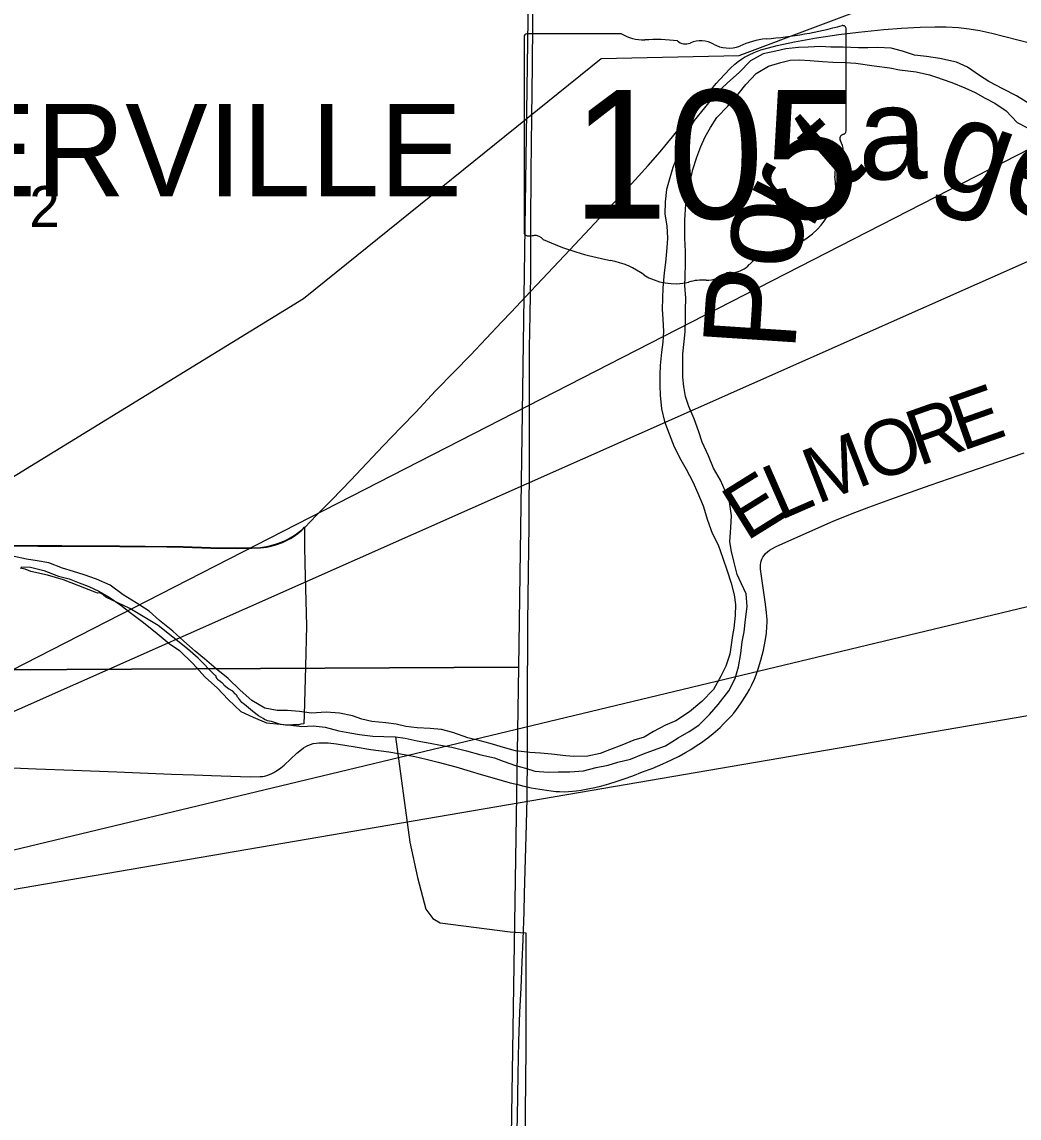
# Model space of a CAD drawing. Extents: x -8.3 to 42.1, y 0 to 22.
# Drawn here: x 6.351 to 7.372, y 16.882 to 18.005 of the extents above; entities that cross this region are included whole.
import ezdxf

# ---------------------------------------------------------------- set-up
doc = ezdxf.new("R2010")
doc.units = 0
for name, color, linetype in [('GM_X_Corporation', 7, 'Continuous'), ('GM_X_Corporation_Text', 7, 'Continuous'), ('GM_X_Major_River', 7, 'Continuous'), ('GM_X_Major_River_Text', 7, 'Continuous'), ('GM_X_Minor_River', 7, 'Continuous'), ('GM_X_Rail_Line', 7, 'Continuous'), ('GM_X_Section', 7, 'Continuous'), ('GM_X_Section_Text', 7, 'Continuous'), ('GM_X_State_Location', 7, 'Continuous'), ('GM_X_State_Route', 7, 'Continuous'), ('GM_X_State_Shield', 7, 'Continuous'), ('GM_X_Township_Road', 7, 'Continuous'), ('GM_X_Township_Road_Text', 7, 'Continuous'), ('SH_Text', 7, 'Continuous')]:
    doc.layers.add(name, color=color, linetype=linetype)

msp = doc.modelspace()

# ---------------------------------------------------------------- linework, layer by layer
at = {"layer": 'GM_X_Corporation'}
msp.add_lwpolyline([(6.3281, 17.4687), (6.3669, 17.4683), (6.3917, 17.4683), (6.4507, 17.4679), (6.4771, 17.4678), (6.4989, 17.4675), (6.5159, 17.4672), (6.5439, 17.4663), (6.5718, 17.4659), (6.5857, 17.466), (6.595, 17.4665), (6.6011, 17.4674), (6.6055, 17.4683), (6.6114, 17.47), (6.6172, 17.4721), (6.6214, 17.474), (6.6254, 17.4762), (6.6294, 17.4786), (6.6331, 17.4813), (6.6372, 17.4846), (6.6401, 17.4875), (6.6402, 17.4676), (6.6406, 17.4498), (6.6423, 17.386), (6.6411, 17.3446), (6.6398, 17.2948), (6.6393, 17.2857), (6.6363, 17.2852), (6.6342, 17.2848), (6.6324, 17.2846), (6.6282, 17.2846), (6.6275, 17.2845), (6.6268, 17.2844), (6.6252, 17.2843), (6.6233, 17.2843), (6.622, 17.2843), (6.6206, 17.2845), (6.6183, 17.2848), (6.6162, 17.285), (6.6146, 17.2854), (6.6142, 17.2854), (6.6136, 17.2856), (6.6134, 17.2857), (6.6123, 17.2862), (6.6104, 17.2867), (6.6093, 17.2871), (6.6084, 17.2874), (6.6064, 17.288), (6.6022, 17.2889), (6.6016, 17.2891), (6.5991, 17.2903), (6.5977, 17.2911), (6.5931, 17.294), (6.5915, 17.2949), (6.5884, 17.2973), (6.5872, 17.2983), (6.5869, 17.2988), (6.5785, 17.3054), (6.576, 17.3077), (6.5729, 17.3116), (6.5722, 17.3123), (6.5716, 17.3131), (6.5712, 17.3138), (6.571, 17.3143), (6.5705, 17.3149), (6.5696, 17.3156), (6.569, 17.3165), (6.5668, 17.319), (6.5624, 17.3217), (6.5613, 17.3224), (6.5592, 17.3239), (6.558, 17.325), (6.557, 17.3262), (6.556, 17.3272), (6.5555, 17.3277), (6.5539, 17.329), (6.552, 17.3303), (6.5519, 17.3304), (6.5513, 17.3309), (6.5509, 17.3316), (6.5505, 17.3323), (6.5502, 17.3329), (6.5496, 17.3332), (6.5496, 17.3347), (6.5489, 17.3352), (6.5484, 17.3357), (6.5313, 17.3529), (6.5204, 17.3626), (6.4902, 17.3865), (6.4613, 17.4039), (6.4367, 17.4155), (6.4344, 17.4174), (6.4327, 17.419), (6.4307, 17.4198), (6.4282, 17.4197), (6.4231, 17.4215), (6.3935, 17.4332), (6.3769, 17.4381), (6.36, 17.4419), (6.354, 17.4441), (6.349, 17.4451)], dxfattribs=at)
at = {"layer": 'GM_X_Major_River'}
for points in [[(7.3833, 17.9203), (7.3692, 17.929), (7.355, 17.9362), (7.3408, 17.9437), (7.3311, 17.95), (7.3188, 17.9583), (7.3075, 17.9635), (7.2906, 17.9673), (7.277, 17.9692), (7.2645, 17.9706), (7.2525, 17.9747), (7.2407, 17.9777), (7.2269, 17.9787), (7.217, 17.9782), (7.2072, 17.9781), (7.1917, 17.9788), (7.1788, 17.9788), (7.1686, 17.9794), (7.1557, 17.9789), (7.1458, 17.9784), (7.1329, 17.9772), (7.1226, 17.9748), (7.1097, 17.9721), (7.0966, 17.9648), (7.085, 17.953), (7.073, 17.9422), (7.061, 17.9308), (7.0496, 17.9166), (7.0391, 17.9036), (7.0312, 17.8905), (7.0256, 17.8785), (7.0223, 17.8687), (7.0171, 17.8556), (7.0133, 17.8427), (7.0108, 17.8329), (7.0094, 17.8204), (7.0091, 17.8079), (7.011, 17.7957), (7.0119, 17.7832), (7.0112, 17.7733), (7.0097, 17.7582), (7.0083, 17.7476), (7.0068, 17.7325), (7.0063, 17.7105), (7.0068, 17.7002), (7.0076, 17.6877), (7.0069, 17.6767), (7.0055, 17.6665), (7.0041, 17.6528), (7.0038, 17.6433), (7.0039, 17.632), (7.0041, 17.6225), (7.0056, 17.6084), (7.0087, 17.5954), (7.0133, 17.5828), (7.0187, 17.5694), (7.0255, 17.5563), (7.031, 17.5467), (7.0378, 17.5336)], [(7.0915, 17.3926), (7.0934, 17.4059), (7.0922, 17.4188), (7.0875, 17.4292), (7.0832, 17.4388), (7.0798, 17.4525), (7.0774, 17.4624), (7.0757, 17.4723), (7.0765, 17.4867), (7.0771, 17.4989), (7.0752, 17.513), (7.0709, 17.5244), (7.0659, 17.5352), (7.059, 17.5475), (7.0537, 17.5602), (7.0472, 17.5744), (7.0437, 17.5847), (7.0391, 17.5981), (7.0337, 17.6107), (7.0302, 17.6211), (7.0285, 17.6314), (7.0276, 17.6409), (7.0276, 17.6545), (7.0275, 17.6648), (7.0289, 17.6773), (7.0299, 17.6871), (7.0302, 17.6989), (7.0301, 17.7099), (7.0304, 17.7216), (7.0296, 17.7346), (7.0298, 17.744), (7.0301, 17.7569), (7.0301, 17.7695), (7.0296, 17.7831), (7.0294, 17.8021), (7.0305, 17.8177), (7.0323, 17.8286), (7.0345, 17.8399), (7.0378, 17.8535), (7.0419, 17.8663), (7.046, 17.8772), (7.0504, 17.887), (7.0559, 17.8967), (7.0623, 17.9068), (7.0735, 17.9183), (7.084, 17.9308), (7.092, 17.9405), (7.1024, 17.9518), (7.1151, 17.9594), (7.1277, 17.9633), (7.1372, 17.9654), (7.1467, 17.9659), (7.1577, 17.9652), (7.1705, 17.9642), (7.1811, 17.9635), (7.1935, 17.9632), (7.2045, 17.9626), (7.2234, 17.9598), (7.2392, 17.9576), (7.2494, 17.9558), (7.2664, 17.9535), (7.28, 17.9505), (7.286, 17.9484), (7.3029, 17.9427), (7.316, 17.9371), (7.3268, 17.9323), (7.3369, 17.9267), (7.347, 17.9216), (7.3586, 17.9137), (7.3696, 17.9017), (7.3797, 17.8965)], [(7.0378, 17.5336), (7.0429, 17.5221), (7.0482, 17.5091), (7.0528, 17.4945), (7.0574, 17.4811), (7.0635, 17.4692), (7.0685, 17.4554), (7.0727, 17.4424), (7.0769, 17.4298), (7.08, 17.418), (7.0813, 17.4081), (7.081, 17.3967), (7.0797, 17.3838), (7.0784, 17.3763), (7.0755, 17.357), (7.0714, 17.3449), (7.0662, 17.3344), (7.0587, 17.3209), (7.047, 17.3087), (7.0343, 17.298), (7.0204, 17.2889), (7.0097, 17.2842), (6.9974, 17.2777), (6.9878, 17.2722), (6.9771, 17.269), (6.9649, 17.264), (6.9523, 17.259), (6.9427, 17.2554), (6.9301, 17.2527), (6.9159, 17.2521), (6.9075, 17.2529), (6.8931, 17.2548), (6.8818, 17.2558), (6.8708, 17.2564), (6.8561, 17.2579), (6.844, 17.2613), (6.8301, 17.2654), (6.82, 17.2683), (6.8072, 17.2713), (6.7918, 17.2769), (6.7805, 17.2799), (6.7688, 17.2809), (6.7555, 17.2816), (6.7438, 17.283), (6.734, 17.2852), (6.7235, 17.2866), (6.7091, 17.2881), (6.6989, 17.2906), (6.6892, 17.2939), (6.676, 17.2965), (6.6624, 17.2975), (6.6472, 17.2968), (6.6351, 17.2982), (6.6227, 17.2993), (6.6121, 17.2995), (6.5996, 17.3017), (6.5862, 17.3096), (6.5743, 17.3202), (6.5618, 17.3322), (6.5495, 17.342), (6.5376, 17.3522), (6.528, 17.36), (6.5165, 17.3705), (6.5054, 17.3807), (6.4917, 17.3916), (6.4809, 17.401), (6.4679, 17.4097), (6.4544, 17.418), (6.4411, 17.4278), (6.4273, 17.4338), (6.4144, 17.4383), (6.4035, 17.4416), (6.3923, 17.4453), (6.3784, 17.4506), (6.3663, 17.4527), (6.3554, 17.4545), (6.3429, 17.4571)], [(6.3499, 17.4467), (6.3597, 17.4461), (6.3733, 17.4427), (6.3883, 17.437), (6.3992, 17.4341), (6.4093, 17.4301), (6.4194, 17.4264), (6.4295, 17.4216), (6.44, 17.4153), (6.4519, 17.4074), (6.4616, 17.3996), (6.4753, 17.3894), (6.4891, 17.3784), (6.5017, 17.3679), (6.5121, 17.3608), (6.5258, 17.3475), (6.5383, 17.3336), (6.5509, 17.3223), (6.562, 17.3106), (6.5749, 17.2985), (6.5877, 17.2925), (6.6012, 17.2869), (6.6151, 17.2854), (6.6261, 17.2844), (6.6374, 17.283), (6.6488, 17.2835), (6.6613, 17.2824), (6.6752, 17.2786), (6.6865, 17.2765), (6.6963, 17.2747), (6.7099, 17.2732), (6.7212, 17.2726), (6.7333, 17.2723), (6.7431, 17.2709), (6.7556, 17.2683), (6.7689, 17.266), (6.7793, 17.264), (6.791, 17.2618), (6.8061, 17.258), (6.8207, 17.2539), (6.8347, 17.2509), (6.8435, 17.2474), (6.8561, 17.2431), (6.8662, 17.2402), (6.876, 17.2373), (6.8896, 17.2362), (6.8998, 17.2364), (6.9116, 17.2365), (6.9256, 17.2376), (6.9386, 17.2411), (6.9511, 17.2435), (6.9608, 17.2463), (6.974, 17.2494), (6.987, 17.2551), (6.9973, 17.2587), (7.0096, 17.2633), (7.0226, 17.2713), (7.0338, 17.2779), (7.0438, 17.2845), (7.0547, 17.2952), (7.0636, 17.3056), (7.0746, 17.3194), (7.0809, 17.3322), (7.0843, 17.3442), (7.0869, 17.3578), (7.0883, 17.3696), (7.0901, 17.3798), (7.0915, 17.3926)]]:
    msp.add_lwpolyline(points, dxfattribs=at)
at = {"layer": 'GM_X_Minor_River'}
msp.add_lwpolyline([(6.7333, 17.2723), (6.7481, 17.1645), (6.7559, 17.1283), (6.7642, 17.0958), (6.7715, 17.0862), (6.779, 17.0818), (6.8507, 17.0725), (6.8666, 17.0717), (6.8667, 16.9529), (6.8644, 16.7253), (6.8617, 16.5857), (6.861, 16.4802), (6.8584, 16.374), (6.8579, 16.325), (6.8551, 16.2708), (6.853, 16.1878), (6.8511, 16.0815), (6.8504, 15.9601), (6.848, 15.8175)], dxfattribs=at)
at = {"layer": 'GM_X_Rail_Line'}
msp.add_lwpolyline([(5.9044, 17.3082), (6.0693, 17.3942), (6.218, 17.4628), (6.6389, 17.7213), (6.9437, 17.9671), (7.085, 17.9703), (7.2495, 18.0325), (7.9103, 18.3409)], dxfattribs=at)
at = {"layer": 'GM_X_Section'}
for points in [[(5.9121, 18.3219), (6.8731, 18.3158), (6.8593, 17.3438), (5.8682, 17.3386), (5.8932, 18.3221)], [(6.8593, 17.3438), (6.8436, 16.3404), (5.8503, 16.3424), (5.8682, 17.3386)]]:
    msp.add_lwpolyline(points, close=True, dxfattribs=at)
at = {"layer": 'GM_X_State_Route'}
for points in [[(6.6404, 17.4869), (6.6522, 17.499), (6.6681, 17.5152), (6.6875, 17.5354), (6.7206, 17.5705), (6.739, 17.5895), (6.7542, 17.605), (6.7742, 17.6267), (6.7937, 17.6468), (6.81, 17.6635), (6.842, 17.6975), (6.8517, 17.7075), (6.8715, 17.7285), (6.878, 17.7354), (6.9117, 17.7712), (6.9573, 17.8197), (6.9787, 17.8429), (6.992, 17.8576), (7.0042, 17.8717), (7.0169, 17.887), (7.025, 17.8972), (7.0321, 17.9059), (7.0492, 17.9265), (7.0617, 17.9418), (7.07, 17.951), (7.0761, 17.9572), (7.0806, 17.9613), (7.0842, 17.9642), (7.0875, 17.9666), (7.0906, 17.9685), (7.0954, 17.9711), (7.1005, 17.9734), (7.1074, 17.976), (7.1151, 17.9783), (7.1241, 17.9806), (7.1417, 17.9842), (7.1643, 17.9884), (7.187, 17.9918), (7.2074, 17.9943), (7.2333, 17.9969), (7.2513, 17.9983), (7.2705, 17.9993), (7.2854, 17.9997), (7.2972, 17.9996), (7.3096, 17.999), (7.3206, 17.9978), (7.3316, 17.996), (7.3437, 17.9933), (7.4238, 17.9728)], [(6.2852, 17.4687), (6.3283, 17.4682), (6.3671, 17.4678), (6.392, 17.4677), (6.4509, 17.4673), (6.4773, 17.4672), (6.4991, 17.4669), (6.5162, 17.4666), (6.5441, 17.4658), (6.572, 17.4654), (6.586, 17.4655), (6.5952, 17.466), (6.6013, 17.4668), (6.6058, 17.4678), (6.6117, 17.4695), (6.6174, 17.4716), (6.6216, 17.4735), (6.6257, 17.4756), (6.6296, 17.4781), (6.6333, 17.4807), (6.6374, 17.4841), (6.6404, 17.4869)]]:
    msp.add_lwpolyline(points, dxfattribs=at)
at = {"layer": 'GM_X_State_Shield'}
for p, q in [((6.865, 17.9892), (6.865, 17.7891)), ((6.9647, 17.9927), (6.8682, 17.9927)), ((7.1946, 17.893), (7.1946, 17.9976)), ((7.1945, 17.893), (7.1946, 17.893))]:
    msp.add_line(p, q, dxfattribs=at)
for centre, major_axis, start_param, end_param in [((7.0772, 18.2655), (0.3495, 0), 4.814394, 5.042369), ((7.1909, 17.9981), (0.00367, 0), 6.141152, 7.989035), ((6.8688, 17.9897), (0.00382, 0), 1.712693, 3.28349), ((6.9877, 18.0159), (0.037, 0), 4.042523, 4.731795), ((7, 17.8803), (0.133, 0), 1.404758, 1.657858), ((7.0302, 17.9907), (0.0107, 0), 3.836095, 5.185415), ((7.0459, 17.9676), (0.0222, 0), 0.950623, 2.079405), ((7.0746, 17.9993), (0.0267, 0), 4.081561, 5.145723), ((7.1217, 17.9316), (0.0703, 0), 1.699011, 2.107814), ((7.1937, 17.8853), (0.00568, 0), 1.883978, 3.671073), ((7.1906, 17.8926), (0.00393, 0), 5.05454, 6.418171), ((7.1576, 17.872), (0.0341, 0), 5.934695, 6.695948), ((7.2077, 17.8492), (0.0248, 0), 2.387724, 3.262537), ((7.0967, 17.8358), (0.0874, 0), 5.101752, 6.440018), ((6.8688, 17.7887), (0.00385, 0), 3.00124, 4.508301), ((6.8694, 17.8092), (0.0294, 0), 4.665946, 4.897461), ((6.8754, 17.7776), (0.0106, 0), 0.519207, 1.627899), ((7.0092, 17.9574), (0.2524, 0), 4.195997, 4.488961), ((7.1336, 17.7329), (0.0479, 0), 1.647645, 2.488434), ((6.934, 17.6992), (0.079, 0), 0.823519, 1.323587), ((7.0729, 17.7697), (0.0282, 0), 4.937069, 5.64225), ((7.0194, 17.7766), (0.0501, 0), 4.026481, 4.996735), ((7.052, 17.7616), (0.0267, 0), 4.691044, 5.507374), ((7.0761, 17.7422), (0.00752, 0), 1.147584, 2.315152), ((7.0483, 17.7074), (0.0412, 0), 1.495662, 1.94098)]:
    msp.add_ellipse(centre, major_axis=major_axis, ratio=0.8, start_param=start_param, end_param=end_param, dxfattribs=at)
at = {"layer": 'GM_X_Township_Road'}
for points in [[(6.8715, 17.7285), (6.8719, 17.7424), (6.8719, 17.7641), (6.8719, 17.7968), (6.8722, 17.8512), (6.8728, 17.9071), (6.8734, 17.96), (6.8743, 18.047), (6.8751, 18.1201), (6.8762, 18.2055), (6.8767, 18.232), (6.8771, 18.2568), (6.8776, 18.2817), (6.8784, 18.3004), (6.8786, 18.3057)], [(6.8681, 17.2212), (6.8683, 17.2435), (6.8684, 17.273), (6.8684, 17.301), (6.8688, 17.3896), (6.8693, 17.4409), (6.87, 17.4891), (6.8705, 17.5621), (6.8705, 17.5963), (6.8704, 17.6352), (6.8704, 17.6709), (6.871, 17.7051), (6.8714, 17.7253), (6.8715, 17.7285)], [(6.8681, 17.2212), (6.8722, 17.2203), (6.8812, 17.2188), (6.8901, 17.2173), (6.8951, 17.2167), (6.8973, 17.2165), (6.9013, 17.2163), (6.9061, 17.2161), (6.9105, 17.2163), (6.9145, 17.2166), (6.9181, 17.2171), (6.9233, 17.2178), (6.9302, 17.2191), (6.9375, 17.2206), (6.9445, 17.2223), (6.9518, 17.2243), (6.9592, 17.2266), (6.9673, 17.2293), (6.9761, 17.2324), (6.9862, 17.2364), (6.996, 17.2401), (7.0069, 17.2448), (7.0159, 17.2488), (7.0238, 17.2527), (7.03, 17.2562), (7.0355, 17.2594), (7.0412, 17.2631), (7.0464, 17.2667), (7.0508, 17.2698), (7.0532, 17.2715), (7.0586, 17.2758), (7.0656, 17.2821), (7.0692, 17.2856), (7.0723, 17.2887), (7.0739, 17.2905), (7.0768, 17.2936), (7.0795, 17.2968), (7.0824, 17.3004), (7.0865, 17.3063), (7.0879, 17.3084), (7.091, 17.3131), (7.0933, 17.3168), (7.0958, 17.321), (7.098, 17.3257), (7.1007, 17.3313), (7.1025, 17.336), (7.1049, 17.3431), (7.1072, 17.3509), (7.1099, 17.3611), (7.1119, 17.3703), (7.1131, 17.3784), (7.1136, 17.3859), (7.1138, 17.3892), (7.1138, 17.3925), (7.1136, 17.3957), (7.1132, 17.3997), (7.1122, 17.4083), (7.1071, 17.444), (7.1069, 17.4461), (7.107, 17.4486), (7.1074, 17.4507), (7.1077, 17.4524), (7.1084, 17.4544), (7.1095, 17.4564), (7.1106, 17.4582), (7.1122, 17.4603), (7.1141, 17.462), (7.1162, 17.4636), (7.1191, 17.4653), (7.1223, 17.4671), (7.1268, 17.4692), (7.1814, 17.4934), (7.1991, 17.5006), (7.2178, 17.5076), (7.2405, 17.5159), (7.2546, 17.5211), (7.2805, 17.5302), (7.3204, 17.5438), (7.3509, 17.5544), (7.3768, 17.5632)], [(6.3412, 17.2405), (6.3655, 17.2396), (6.4034, 17.2383), (6.4481, 17.2366), (6.504, 17.2343), (6.527, 17.2335), (6.545, 17.2328), (6.5846, 17.2314), (6.5948, 17.2317), (6.5973, 17.2319), (6.5993, 17.2322), (6.6015, 17.2328), (6.6041, 17.2338), (6.6065, 17.2348), (6.6087, 17.2359), (6.6107, 17.2371), (6.6126, 17.2383), (6.6157, 17.2405), (6.6192, 17.2432), (6.6323, 17.2556), (6.6371, 17.2595), (6.6392, 17.2611), (6.6414, 17.2625), (6.6436, 17.2635), (6.6464, 17.2646), (6.6491, 17.2654), (6.6519, 17.266), (6.6549, 17.2663), (6.6582, 17.2664), (6.661, 17.2663), (6.6642, 17.2661), (6.6728, 17.2651), (6.6918, 17.2621), (6.708, 17.2594), (6.7263, 17.2569), (6.7441, 17.2539), (6.7532, 17.2521), (6.7648, 17.2496), (6.7771, 17.2464), (6.795, 17.2415), (6.8097, 17.2373), (6.8208, 17.2339), (6.8342, 17.2299), (6.8506, 17.2252), (6.8585, 17.2234), (6.8645, 17.222), (6.8681, 17.2212)], [(6.8503, 16.3361), (6.8505, 16.3485), (6.8511, 16.3936), (6.8526, 16.521), (6.853, 16.5537), (6.8534, 16.5987), (6.8535, 16.6189), (6.8539, 16.6562), (6.8543, 16.6904), (6.8549, 16.7371), (6.8555, 16.7759), (6.8581, 16.8831), (6.859, 16.9266), (6.8596, 16.9608), (6.8606, 16.9904), (6.8618, 17.0152), (6.8629, 17.0416), (6.8638, 17.0649), (6.865, 17.0928), (6.8655, 17.1115), (6.8673, 17.1829), (6.868, 17.2093), (6.8681, 17.2212)]]:
    msp.add_lwpolyline(points, dxfattribs=at)
at = {"layer": 'SH_Text'}
for points in [[(9.5811, 19.002), (5.7134, 17.0195), (9.5811, 18.737)], [(9.5811, 17.9343), (5.7594, 17.0162), (9.5811, 17.6715)]]:
    msp.add_lwpolyline(points, close=True, dxfattribs=at)

# ---------------------------------------------------------------- texts
at = {"layer": 'GM_X_Corporation_Text'}
msp.add_text('PEMBERVILLE', height=0.094697, rotation=0, dxfattribs=at).set_placement((5.9217, 17.8261))
at = {"layer": 'GM_X_Major_River_Text'}
for s, height, rotation, p in [('t', 0.0948, 41.2253, (7.1906, 17.8298)), ('a', 0.0948, 1.2236, (7.2078, 17.8429)), ('ge', 0.09475, 341.2231, (7.2823, 17.8407)), ('r', 0.0948, 61.2258, (7.1585, 17.7903)), ('Po', 0.09476, 86.2254, (7.1422, 17.6661))]:
    msp.add_text(s, height=height, rotation=rotation, dxfattribs=at).set_placement(p)
at = {"layer": 'GM_X_Section_Text'}
msp.add_text('2', height=0.0419, rotation=0, dxfattribs=at).set_placement((6.3584, 17.7947))
at = {"layer": 'GM_X_State_Location'}
for s in ['s', 'r']:
    msp.add_text(s, height=0.000189, dxfattribs=at).set_placement((7.0261, 17.8759))
msp.add_text('105', height=0.000189, rotation=0, dxfattribs=at).set_placement((6.9592, 17.8621))
at = {"layer": 'GM_X_State_Shield'}
msp.add_text('105', height=0.13184, dxfattribs=at).set_placement((6.9141, 17.8032))
at = {"layer": 'GM_X_Township_Road_Text'}
for s, rotation, p in [('E', 19.4556, (7.3131, 17.5648)), ('R', 19.4039, (7.2691, 17.5493)), ('O', 19.4752, (7.2219, 17.5326)), ('M', 21.2793, (7.1649, 17.5104)), ('L', 23.6488, (7.1266, 17.4936)), ('E', 31.8641, (7.0924, 17.4722))]:
    msp.add_text(s, height=0.0568, rotation=rotation, dxfattribs=at).set_placement(p)

doc.saveas('drawing.dxf')
